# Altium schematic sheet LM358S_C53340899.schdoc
size 127 x 101 mm
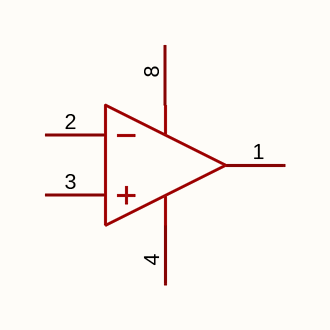
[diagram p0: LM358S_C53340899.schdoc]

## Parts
U?  lm358s_c53340899  [SOIC-8_L5.0-W4.0-P1.27-LS6.0-BL]  (value not drawn)  (part A of 2)

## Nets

Not connected (* = marked no-connect by the designer): U? 1(OUT1) 2(IN1-) 3(IN1+) 4(VEE) 8(VCC)

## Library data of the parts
U? = lm358s_c53340899: 放大器数:2;轨到轨:-;增益带宽积(GBW):1MHz;输入失调电压(Vos):2mV;压摆率(SR):400V/ms;输入偏置电流(Ib):50nA;; Manufacturer: TECH PUBLIC(台舟); ManufacturerPart: LM358S; AddInBom: yes; ModelId: 7abc64c95a1a4a04a4ef38f9097c870b; ModelTransform: 192.913,236.22,0,0,0,0,0,0,0; Number of Channels: 2; Gain Bandwidth Product: 1MHz; Vos - Input Offset Voltage: 2mV; Ib - Input Bias Current: 50nA; Input Offset Current(Ios): 10nA; Common Mode Rejection Ratio(CMRR): 80dB; Quiescent Current: 500uA; Output Current: 40mA; Single supply: 3V~24V; Dual Supply: -12V~-1.5V；1.5V~12V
